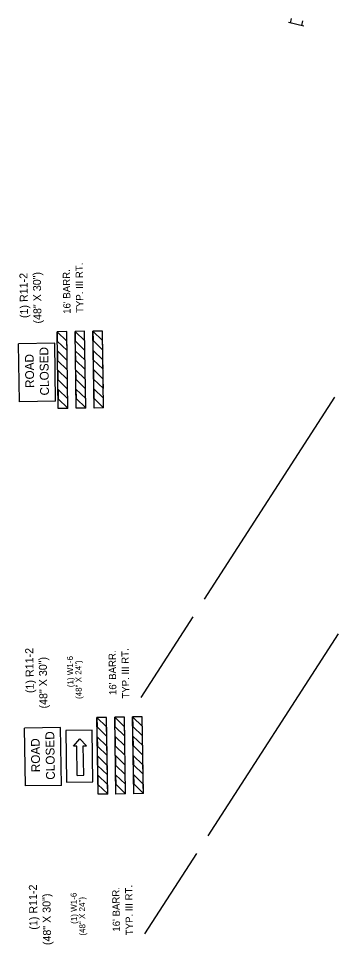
# Model space of a CAD drawing. Extents: x 1770139 to 1773492, y 718230 to 727190.
# Drawn here: x 1773172 to 1773492, y 719211 to 720137 of the extents above; entities that cross this region are included whole.
import ezdxf

# ---------------------------------------------------------------- set-up
doc = ezdxf.new("R2010")
doc.units = 0
doc.layers.add('R_Border PE', color=7, linetype='Continuous')
doc.layers.add('R_MOT', color=7, linetype='Continuous')

msp = doc.modelspace()

# ---------------------------------------------------------------- linework, layer by layer
at = {"layer": 'R_Border PE'}
for p, q in [((1773357.72, 719556.23), (1773487.99, 719758.35)), ((1773294.52, 719458.17), (1773346.42, 719538.69)), ((1773361.36, 719319.51), (1773491.63, 719521.64)), ((1773298.17, 719221.46), (1773350.06, 719301.98))]:
    msp.add_line(p, q, dxfattribs=at)
at = {"layer": 'R_MOT'}
for p, q in [((1773456.85, 720129.75), (1773441.63, 720133.11)), ((1773443.71, 720132.65), (1773444.73, 720137.26)), ((1773454.92, 720130.17), (1773455.94, 720134.78)), ((1773219.98, 719824.06), (1773210.33, 719823.91)), ((1773211.52, 719747.05), (1773210.33, 719823.91)), ((1773219.96, 719824), (1773219.9, 719824.06)), ((1773221.17, 719747.2), (1773219.98, 719824.06)), ((1773237.85, 719824.34), (1773228.22, 719824.19)), ((1773237.85, 719824.34), (1773228.22, 719824.19)), ((1773229.41, 719747.32), (1773228.22, 719824.19)), ((1773239.03, 719747.47), (1773237.85, 719824.34)), ((1773255.68, 719824.61), (1773246.06, 719824.46)), ((1773247.24, 719747.6), (1773246.06, 719824.46)), ((1773256.87, 719747.75), (1773255.68, 719824.61)), ((1773207.96, 719812.42), (1773171.75, 719811.87)), ((1773172.65, 719753.91), (1773171.75, 719811.87)), ((1773208.85, 719754.47), (1773207.96, 719812.42)), ((1773208.85, 719754.47), (1773172.65, 719753.91)), ((1773221.17, 719747.2), (1773211.52, 719747.05)), ((1773239.03, 719747.47), (1773229.41, 719747.32)), ((1773256.87, 719747.75), (1773247.24, 719747.6)), ((1773259.74, 719438.16), (1773250.08, 719438.01)), ((1773251.27, 719361.15), (1773250.08, 719438.01)), ((1773259.71, 719438.11), (1773259.65, 719438.16)), ((1773260.92, 719361.3), (1773259.74, 719438.16)), ((1773277.6, 719438.44), (1773267.98, 719438.29)), ((1773277.6, 719438.44), (1773267.98, 719438.29)), ((1773269.16, 719361.42), (1773267.98, 719438.29)), ((1773278.78, 719361.57), (1773277.6, 719438.44)), ((1773295.43, 719438.71), (1773285.81, 719438.56)), ((1773286.99, 719361.7), (1773285.81, 719438.56)), ((1773296.62, 719361.85), (1773295.43, 719438.71)), ((1773213.88, 719428), (1773177.68, 719427.44)), ((1773214.77, 719370.04), (1773213.88, 719428)), ((1773178.57, 719369.48), (1773177.68, 719427.44)), ((1773226.66, 719409.4), (1773233.1, 719416.68)), ((1773229.94, 719409.45), (1773226.66, 719409.4)), ((1773230.39, 719380.07), (1773229.94, 719409.45)), ((1773233.1, 719416.68), (1773239.75, 719409.61)), ((1773236.48, 719409.56), (1773239.75, 719409.61)), ((1773236.93, 719380.17), (1773236.48, 719409.56)), ((1773230.39, 719380.07), (1773236.93, 719380.17)), ((1773214.77, 719370.04), (1773178.57, 719369.48)), ((1773260.92, 719361.3), (1773251.27, 719361.15)), ((1773278.78, 719361.57), (1773269.16, 719361.42)), ((1773296.62, 719361.85), (1773286.99, 719361.7))]:
    msp.add_line(p, q, dxfattribs=at)
for points in [[(1773210.33, 719823.91), (1773210.51, 719814.46), (1773220.25, 719805.02), (1773220.1, 719814.44)], [(1773228.22, 719824.19), (1773228.4, 719814.74), (1773238.14, 719805.29), (1773237.99, 719814.72)], [(1773246.06, 719824.46), (1773246.23, 719815.02), (1773255.97, 719805.57), (1773255.83, 719814.99)], [(1773210.63, 719804.71), (1773210.8, 719795.26), (1773220.54, 719785.81), (1773220.4, 719795.23)], [(1773228.52, 719804.98), (1773228.69, 719795.53), (1773238.44, 719786.09), (1773238.29, 719795.51)], [(1773246.35, 719805.26), (1773246.53, 719795.81), (1773256.27, 719786.36), (1773256.12, 719795.78)], [(1773210.92, 719785.5), (1773211.1, 719776.05), (1773220.84, 719766.6), (1773220.7, 719776.03)], [(1773228.82, 719785.78), (1773228.99, 719776.33), (1773238.73, 719766.88), (1773238.59, 719776.3)], [(1773246.65, 719786.05), (1773246.82, 719776.6), (1773256.57, 719767.15), (1773256.42, 719776.58)], [(1773211.22, 719766.29), (1773211.39, 719756.84), (1773221.14, 719747.4), (1773220.99, 719756.82)], [(1773229.11, 719766.57), (1773229.29, 719757.12), (1773239.03, 719747.67), (1773238.88, 719757.09)], [(1773246.95, 719766.84), (1773247.12, 719757.39), (1773256.86, 719747.95), (1773256.72, 719757.37)], [(1773250.08, 719438.01), (1773250.26, 719428.56), (1773260, 719419.12), (1773259.86, 719428.54)], [(1773267.98, 719438.29), (1773268.15, 719428.84), (1773277.89, 719419.39), (1773277.75, 719428.82)], [(1773285.81, 719438.56), (1773285.98, 719429.12), (1773295.73, 719419.67), (1773295.58, 719429.09)], [(1773218.93, 719424.86), (1773219.72, 719373.34), (1773246.07, 719373.74), (1773245.28, 719425.27)], [(1773250.38, 719418.81), (1773250.56, 719409.36), (1773260.3, 719399.91), (1773260.15, 719409.33)], [(1773268.27, 719419.08), (1773268.45, 719409.63), (1773278.19, 719400.19), (1773278.04, 719409.61)], [(1773286.11, 719419.36), (1773286.28, 719409.91), (1773296.02, 719400.46), (1773295.88, 719409.88)], [(1773268.57, 719399.88), (1773268.74, 719390.43), (1773278.48, 719380.98), (1773278.34, 719390.4)], [(1773286.4, 719400.15), (1773286.58, 719390.7), (1773296.32, 719381.25), (1773296.17, 719390.68)], [(1773250.68, 719399.6), (1773250.85, 719390.15), (1773260.59, 719380.7), (1773260.45, 719390.13)], [(1773250.97, 719380.39), (1773251.15, 719370.94), (1773260.89, 719361.5), (1773260.74, 719370.92)], [(1773268.86, 719380.67), (1773269.04, 719371.22), (1773278.78, 719361.77), (1773278.64, 719371.19)], [(1773286.7, 719380.94), (1773286.87, 719371.49), (1773296.61, 719362.05), (1773296.47, 719371.47)]]:
    msp.add_lwpolyline(points, close=True, dxfattribs=at)

# ---------------------------------------------------------------- texts
for s, height, p in [('TYP. III RT.', 7.2036, (1773236.65, 719842.77)), ('(1) R11-2', 8.004, (1773181.32, 719837.65)), ('(48" X 30")', 8.004, (1773194.79, 719832.18)), ("16' BARR.", 7.204, (1773223.79, 719841.86)), ('CLOSED', 8.817, (1773202.22, 719760.22)), ('ROAD', 8.774, (1773187.41, 719767.77)), ('(1) R11-2', 8.004, (1773187.1, 719462.48)), ("16' BARR.", 7.204, (1773269.61, 719460.51)), ('TYP. III RT.', 7.2036, (1773282.54, 719456.96)), ('(48" X 30")', 8.004, (1773200.73, 719447.06)), ('(1) W1-6', 6, (1773226.59, 719468.34)), ('(48" X 24")', 6, (1773235.03, 719456.54)), ('CLOSED', 8.817, (1773208.14, 719375.79)), ('ROAD', 8.774, (1773193.33, 719383.35)), ('(1) R11-2', 8.004, (1773190.75, 719225.77)), ('(48" X 30")', 8.004, (1773204.37, 719210.34)), ('(1) W1-6', 6, (1773230.24, 719231.62)), ("16' BARR.", 7.204, (1773273.26, 719223.79)), ('TYP. III RT.', 7.2036, (1773286.19, 719220.25)), ('(48" X 24")', 6, (1773238.67, 719219.82))]:
    msp.add_text(s, height=height, rotation=90.88269, dxfattribs=at).set_placement(p)

doc.saveas('drawing.dxf')
